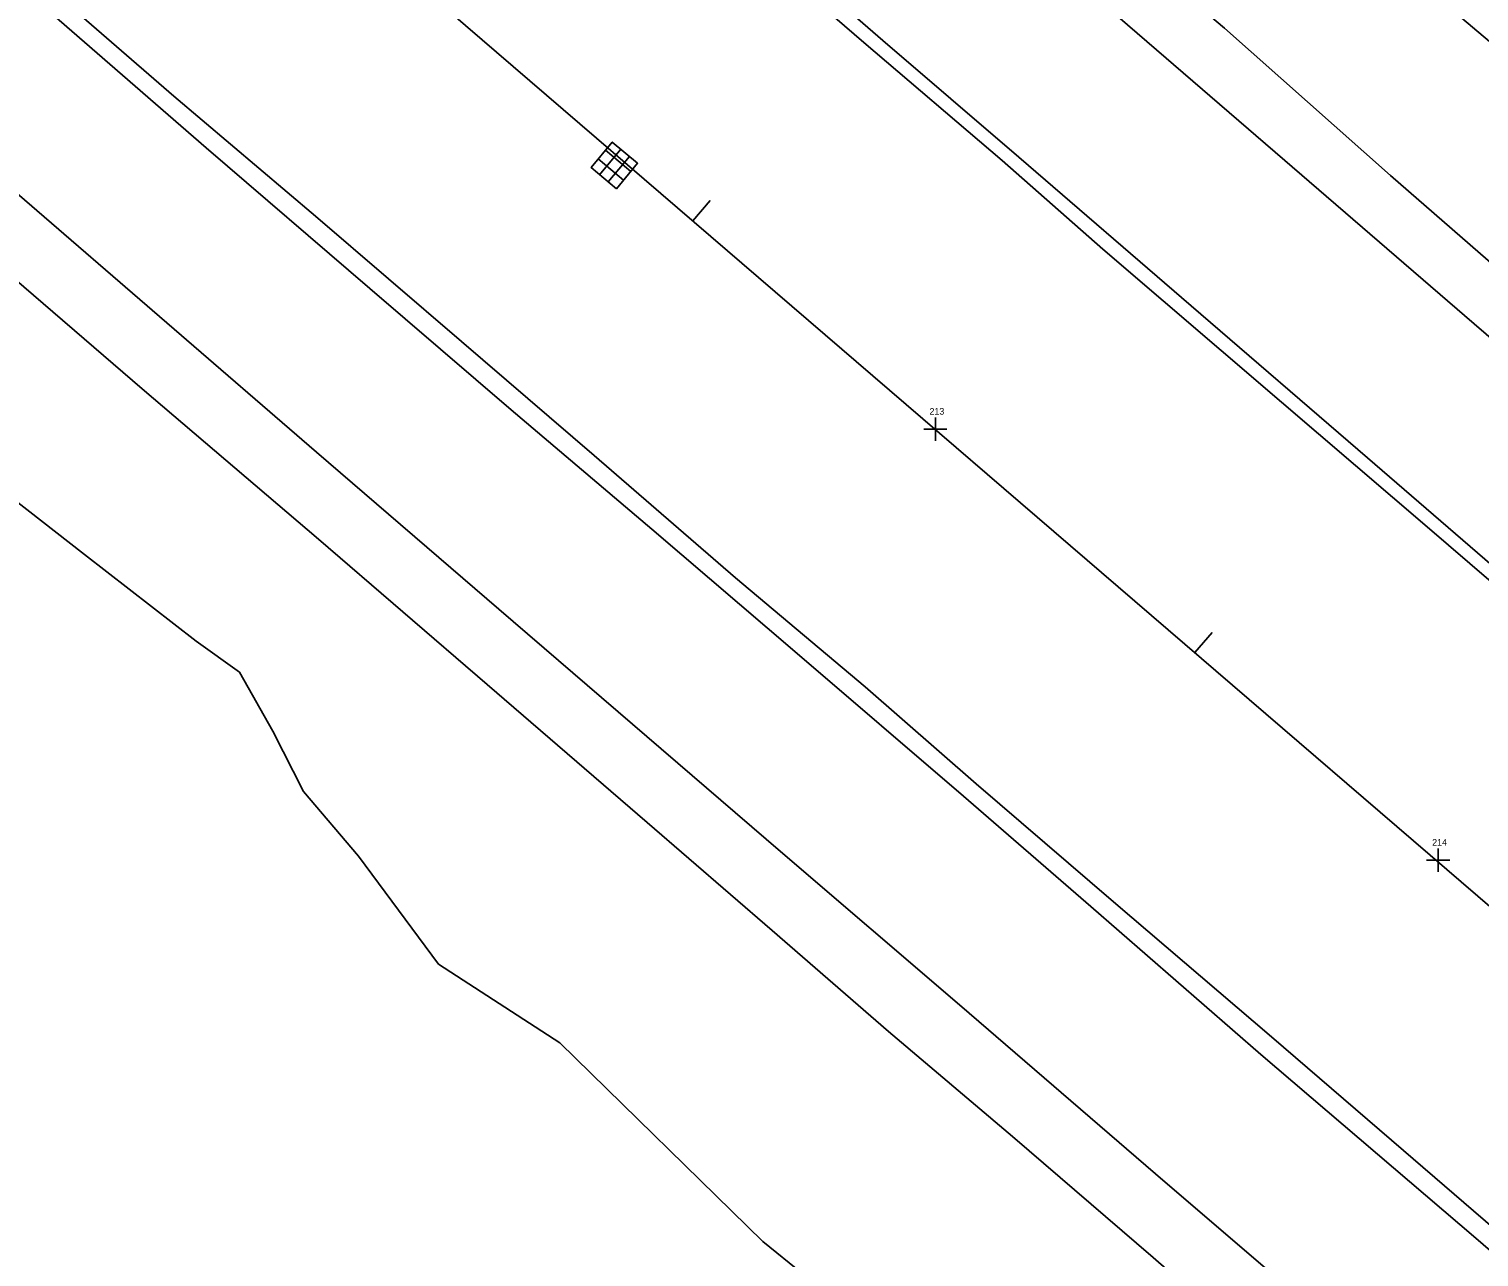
# Model space of a CAD drawing. Extents: x 2076109 to 2080761, y 592812 to 596750.
# Drawn here: x 2076459.2 to 2076678.1, y 596269 to 596454.5 of the extents above; entities that cross this region are included whole.
import ezdxf

# ---------------------------------------------------------------- set-up
doc = ezdxf.new("R2010")
doc.units = 0
for name, color, linetype in [('Default', 7, 'Continuous'), ('RD_EX_DR_Inlet', 7, 'Continuous'), ('RD_EX_Fence_ChLk', 7, 'Continuous'), ('RD_EX_Misc', 7, 'Continuous'), ('RD_EX_Road', 7, 'Continuous'), ('RD_EX_VEG', 7, 'Continuous'), ('RD_HC_Cl', 7, 'Continuous'), ('RD_HC_Data_Tic', 7, 'Continuous')]:
    doc.layers.add(name, color=color, linetype=linetype)

msp = doc.modelspace()

# ---------------------------------------------------------------- linework, layer by layer
at = {"layer": 'Default'}
for p, q in [((2076596.04, 596395.79), (2076596.04, 596392.29)), ((2076596.04, 596395.79), (2076596.04, 596392.29)), ((2076597.79, 596394.04), (2076594.29, 596394.04)), ((2076597.79, 596394.04), (2076594.29, 596394.04)), ((2076671.95, 596330.69), (2076671.95, 596327.19)), ((2076671.95, 596330.69), (2076671.95, 596327.19)), ((2076673.7, 596328.94), (2076670.2, 596328.94)), ((2076673.7, 596328.94), (2076670.2, 596328.94))]:
    msp.add_line(p, q, dxfattribs=at)
at = {"layer": 'RD_EX_DR_Inlet'}
for p, q in [((2076545.13, 596434.88), (2076548.96, 596431.67)), ((2076545.13, 596434.88), (2076548.96, 596431.67)), ((2076545.34, 596432.48), (2076548.55, 596436.32)), ((2076545.34, 596432.48), (2076548.55, 596436.32)), ((2076546.22, 596436.18), (2076550.05, 596432.97)), ((2076546.22, 596436.18), (2076550.05, 596432.97)), ((2076546.64, 596431.39), (2076549.86, 596435.22)), ((2076546.64, 596431.39), (2076549.86, 596435.22))]:
    msp.add_line(p, q, dxfattribs=at)
msp.add_lwpolyline([(2076547.87, 596430.36), (2076544.04, 596433.57), (2076547.25, 596437.41), (2076551.08, 596434.2)], close=True, dxfattribs=at)
msp.add_lwpolyline([(2076547.87, 596430.36), (2076544.04, 596433.57), (2076547.25, 596437.41), (2076551.08, 596434.2)], close=True, dxfattribs=at)
at = {"layer": 'RD_EX_Fence_ChLk'}
msp.add_lwpolyline([(2076421.67, 596703.84), (2076420.04, 596678.46), (2076435, 596664.99), (2076476.98, 596628.77), (2076494.9, 596613.54), (2076529.02, 596583.47), (2076547.46, 596566.35), (2076588.83, 596531.53), (2076656.07, 596472.58), (2076690.89, 596443.2), (2076724.42, 596413.81), (2076777.76, 596368.9), (2076804.64, 596345.73), (2076822.97, 596329.73)], dxfattribs=at)
msp.add_lwpolyline([(2076421.67, 596703.84), (2076420.04, 596678.46), (2076435, 596664.99), (2076476.98, 596628.77), (2076494.9, 596613.54), (2076529.02, 596583.47), (2076547.46, 596566.35), (2076588.83, 596531.53), (2076656.07, 596472.58), (2076690.89, 596443.2), (2076724.42, 596413.81), (2076777.76, 596368.9), (2076804.64, 596345.73), (2076822.97, 596329.73)], dxfattribs=at)
at = {"layer": 'RD_EX_Misc'}
for points in [[(2076810.47, 596295.64), (2076777.15, 596324.36), (2076741.65, 596354.97), (2076702.03, 596388.72), (2076677.4, 596409.97), (2076647.32, 596435.89), (2076621.03, 596458.58), (2076590.12, 596485.04), (2076559.73, 596511.07), (2076528.18, 596538.3), (2076511.92, 596552.28), (2076473.05, 596585.81), (2076454.39, 596601.84), (2076432.84, 596620.26), (2076409.88, 596640.05), (2076391.02, 596656.42), (2076366.25, 596677.71), (2076342.59, 596698.16), (2076317.7, 596719.66), (2076298.57, 596736.16), (2076283.82, 596748.95)], [(2076792.25, 596277.09), (2076766.6, 596299.24), (2076739.85, 596322.1), (2076705.21, 596352.04), (2076683.44, 596370.57), (2076661.29, 596389.7), (2076634.65, 596412.67), (2076608.65, 596435.12), (2076588.09, 596452.73), (2076560.2, 596476.97), (2076539.56, 596494.65), (2076513.35, 596516.99), (2076492.55, 596535.23), (2076471.22, 596553.49), (2076440.45, 596579.86), (2076417.79, 596599.46), (2076392.71, 596620.95), (2076369.17, 596640.89), (2076350.77, 596656.67), (2076332.26, 596672.64), (2076312.58, 596689.46), (2076285.06, 596712.98), (2076260.58, 596734.4)], [(2076740.94, 596217.33), (2076702.64, 596250.28), (2076677.66, 596271.86), (2076645.18, 596299.61), (2076619.49, 596321.95), (2076600.27, 596338.6), (2076575.16, 596360.14), (2076553.23, 596378.95), (2076531.96, 596396.96), (2076510.67, 596415.29), (2076485.91, 596436.55), (2076449.13, 596468.49), (2076415.58, 596497.48), (2076388.85, 596520.39), (2076367.84, 596538.36), (2076329.1, 596571.56), (2076304.36, 596593.15), (2076264.2, 596627.43), (2076241.51, 596646.82), (2076209.02, 596674.79), (2076186.24, 596694.4)], [(2076721.01, 596202.46), (2076680.46, 596237.44), (2076654.71, 596259.75), (2076629.28, 596281.56), (2076599.69, 596307.11), (2076572.67, 596330.24), (2076530.13, 596366.86), (2076502.58, 596390.56), (2076457.41, 596429.64), (2076427.11, 596455.77), (2076391.9, 596485.98), (2076363.12, 596510.6), (2076333.1, 596536.48), (2076305.12, 596560.38), (2076269.62, 596590.83), (2076221.74, 596631.75), (2076198.44, 596651.63), (2076167.21, 596678.59)]]:
    msp.add_lwpolyline(points, dxfattribs=at)
at = {"layer": 'RD_EX_Road'}
for points in [[(2076295.81, 596750.03), (2076327.33, 596722.94), (2076360.43, 596694.1), (2076392.1, 596666.86), (2076422.24, 596640.73), (2076455.24, 596612.56), (2076486.01, 596586.14), (2076511.22, 596564.37), (2076545.63, 596535.19), (2076573.69, 596510.93), (2076594.17, 596493.79), (2076616.52, 596474.15), (2076639.68, 596454.59), (2076664.74, 596432.37), (2076686.11, 596413.8), (2076717.68, 596386.95), (2076745.58, 596362.77), (2076775.65, 596337.23), (2076797.83, 596318.25), (2076816.41, 596301.99)], [(2076790.96, 596275.94), (2076766.19, 596297.13), (2076743.02, 596316.93), (2076725.56, 596332.03), (2076694.64, 596358.37), (2076670.64, 596379.01), (2076648.31, 596398.11), (2076621.33, 596421.25), (2076606.1, 596434.61), (2076585.26, 596452.43), (2076568.05, 596467.31), (2076541.22, 596490.38), (2076523.49, 596505.54), (2076502.2, 596523.86), (2076469.84, 596552.11), (2076441.78, 596576.24), (2076412.01, 596601.82), (2076388.5, 596622.07), (2076362.03, 596644.66), (2076330.25, 596672.15), (2076299.41, 596698.57), (2076259.14, 596733.27)], [(2076700.01, 596207.77), (2076673.17, 596230.79), (2076648.65, 596251.71), (2076628.91, 596268.94), (2076607.7, 596287.19), (2076588.94, 596303.09), (2076571.37, 596318.34), (2076552.54, 596334.64), (2076528.34, 596355.5), (2076502.89, 596377.41), (2076476.27, 596400.16), (2076453.98, 596419.34), (2076424.28, 596444.72), (2076401.96, 596464.06)], [(2076461.47, 596461.35), (2076481.07, 596444.32), (2076502.42, 596426.23), (2076524.51, 596407.27), (2076544.52, 596390.07), (2076565.87, 596371.58), (2076585.42, 596355.12), (2076602.18, 596340.46), (2076622.95, 596322.64), (2076646.77, 596302.25), (2076666.71, 596285.1), (2076682.01, 596271.9)]]:
    msp.add_lwpolyline(points, dxfattribs=at)
at = {"layer": 'RD_EX_VEG'}
msp.add_lwpolyline([(2076351.39, 596466.67), (2076366.12, 596451.71), (2076379.81, 596449.65), (2076385.88, 596441.2), (2076401.39, 596422.01), (2076415.1, 596415.95), (2076431.41, 596397.06), (2076450.09, 596388.69), (2076467.56, 596375.13), (2076484.4, 596362.04), (2076490.96, 596357.32), (2076495.98, 596348.43), (2076500.64, 596339.34), (2076508.91, 596329.56), (2076521.02, 596313.26), (2076539.33, 596301.37), (2076569.99, 596271.34), (2076600.43, 596246.7), (2076641.34, 596210.73), (2076664.34, 596190.24), (2076679.26, 596175.52)], dxfattribs=at)
at = {"layer": 'RD_HC_Cl'}
msp.add_line((2076186.59, 596746.26), (2077404.89, 595698.18), dxfattribs=at)
at = {"layer": 'RD_HC_Data_Tic'}
for p, q in [((2076559.41, 596425.53), (2076562.02, 596428.56)), ((2076559.41, 596425.53), (2076562.02, 596428.56)), ((2076635.22, 596360.31), (2076637.83, 596363.35)), ((2076635.22, 596360.31), (2076637.83, 596363.35))]:
    msp.add_line(p, q, dxfattribs=at)

# ---------------------------------------------------------------- texts
at = {"layer": 'Default'}
for s, p in [('213', (2076595.15, 596396.24)), ('213', (2076595.15, 596396.24)), ('214', (2076671.05, 596331.14)), ('214', (2076671.05, 596331.14))]:
    msp.add_text(s, height=1, dxfattribs=at).set_placement(p)

doc.saveas('drawing.dxf')
